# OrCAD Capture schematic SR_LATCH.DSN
size A
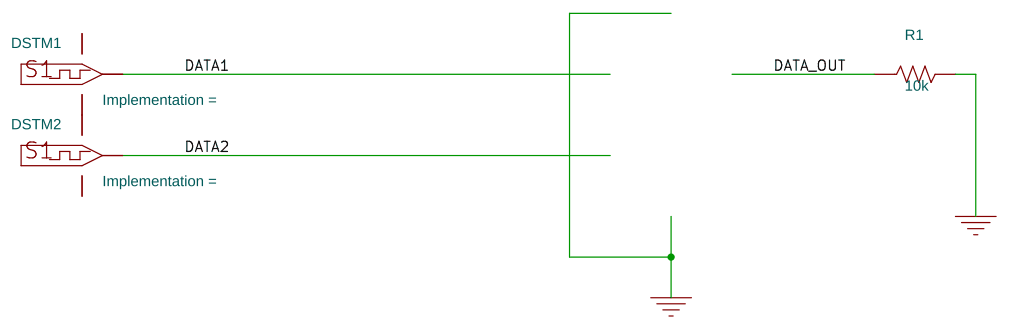
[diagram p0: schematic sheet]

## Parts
DSTM1  DigStim1
DSTM2  DigStim1
R1  10k  [AXRC05]

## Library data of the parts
DSTM1 DSTM2 = DigStim1
R1 = R

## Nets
GND: DSTM1.3(GND) DSTM2.3(GND)
VCC: DSTM1.2(VCC) DSTM2.2(VCC)
0: R1.2
DATA1: DSTM1.OUT
DATA2: DSTM2.OUT
DATA_OUT: R1.1
